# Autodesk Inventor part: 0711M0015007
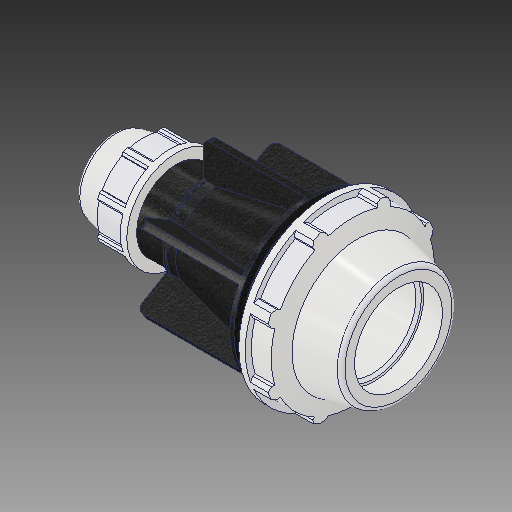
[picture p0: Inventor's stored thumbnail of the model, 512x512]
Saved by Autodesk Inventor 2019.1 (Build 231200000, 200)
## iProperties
Created: 2017-02
Part Number: 0711M0015007
Material: PVC-Piping
Description: PLASSON REDUCING COUPLER 1 1/4'' - 1''
Document SubType Name: Modeling
Designer: KIM
Mass: 92.6774 g
Surface Area: 199.44 cm^2
Volume: 66.1981 cm^3
Density: 1.4 g/cm^3
Appearance: PTFE
Author: KIM
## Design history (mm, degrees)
derived "0711M0.ipt"
feature "Solid1::0711M0.ipt"
tag "TaggingFeature1"
body "Solid1"
other parameters: "d_" = 48.1, "E_" = 96.012, "H_" = 156, "l_" = 54.102, "d_1" = 26.6, "E_1" = 54.102, "l_1" = 58, "d96" = 10.6292, "d2" = 48.1, "d4" = 13, "d5" = 22.28571, "d7" = 96.012, "d9" = 22.28571, "d11" = 2.22857, "d12" = 76.8096, "d13" = 120 deg, "d14" = 62.53, "d15" = 12 deg, "d16" = 86.4108, "d18" = 2.405, "d19" = 35 deg, "d20" = 17.5 deg, "d21" = 89.29116, "d23" = 0, "d25" = 360 deg, "d27" = 1.92024, "d42" = 17.16, "d46" = 1.443, "d51" = 156, "d52" = 53.7931, "d53" = 12 deg, "d54" = 54.102, "d56" = 39.9, "d57" = 26.6, "d58" = 43.29, "d59" = 23.94, "d60" = 48.6918, "d61" = 43.2816, "d62" = 15.6, "d63" = 18.72, "d64" = 120 deg, "d65" = 54.102, "d68" = 11.14286, "d74" = 50.31486, "d75" = 35 deg, "d76" = 17.5 deg, "d78" = 0, "d80" = 360 deg, "d85" = 1.08204, "d88" = 0.532, "d93" = 58, "d94" = 67.2084, "d97" = 3.54307, "d98" = 3.6068, "d99" = 0, "d100" = 3.84048, "d102" = 360 deg, "d104" = 2, "d106" = 0, "d107" = 3.6068, "d108" = 0, "d109" = 3.6068, "d110" = 0
